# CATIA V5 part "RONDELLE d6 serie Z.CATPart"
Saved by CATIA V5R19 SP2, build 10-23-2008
Part number: RONDELLE d6 serie Z
Bounding box of the stored display mesh (mm): x -8 to 8, y -8 to 8, z 0 to 2.4
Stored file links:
  D:\SCHOOL\FRANCE\BANC_POUTRE_EN_MOUSSE\RONDELLE d6 serie Z.CATPart
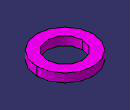
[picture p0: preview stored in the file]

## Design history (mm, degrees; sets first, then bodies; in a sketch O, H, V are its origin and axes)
AxisSystem1: origin (0, 0, 0), X (1, 0, 0), Y (0, 1, 0), Z (0, 0, 1)
Set1
  Sketch1 on XY plane of AxisSystem1, origin (0, 0, 0), H (1, 0, 0), V (0, 1, 0)
    circle A1 centre (0, 0) radius 5
    circle A2 centre (0, 0) radius 8
    radius A1 = 5
    radius A2 = 8
Body1 (main body)
  Pad1: profile Sketch1, direction (0, 0, 1), length 2.4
